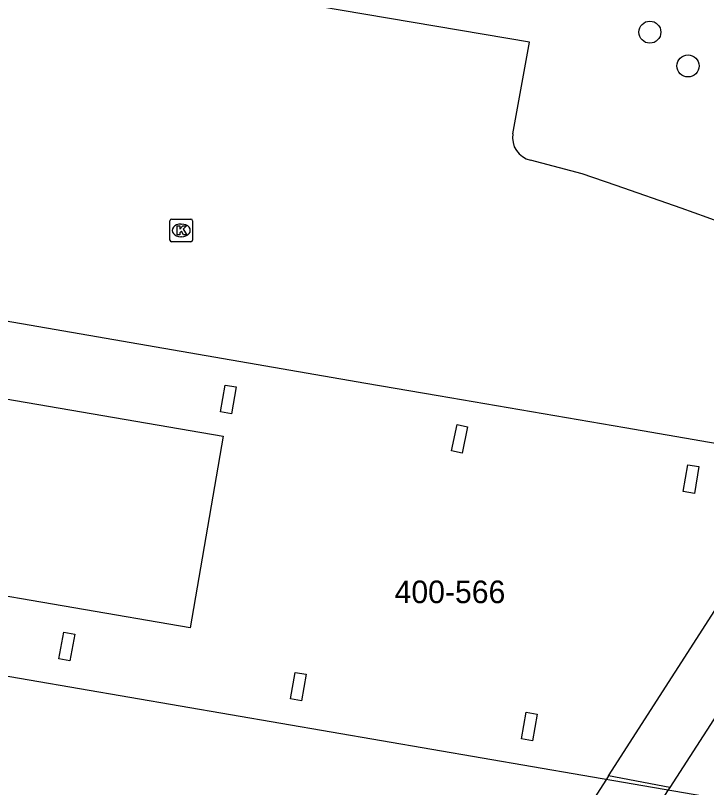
# Model space of a CAD drawing. Extents: x 161258 to 161838, y 380836 to 381727.
# Drawn here: x 161552.64 to 161583.27, y 381006.83 to 381041.03 of the extents above; entities that cross this region are included whole.
import ezdxf

# ---------------------------------------------------------------- set-up
doc = ezdxf.new("R2010")
doc.units = 0
for name, color, linetype in [('IMGEO_Boom', 7, 'Continuous'), ('IMGEO_Fietspad_gesloten', 7, 'Continuous'), ('IMGEO_Groenvoorziening', 7, 'Continuous'), ('IMGEO_Kolk', 7, 'Continuous'), ('IMGEO_Pand', 7, 'Continuous'), ('IMGEO_Pand_nummerreeks', 7, 'Continuous'), ('IMGEO_Pand_overbouw', 7, 'Continuous'), ('IMGEO_Voetpad_open', 7, 'Continuous')]:
    doc.layers.add(name, color=color, linetype=linetype)

msp = doc.modelspace()

# ---------------------------------------------------------------- linework, layer by layer
at = {"layer": 'IMGEO_Boom'}
for centre in [(161580.754, 381040.286), (161582.445, 381038.792)]:
    msp.add_circle(centre, 0.489, dxfattribs=at)
at = {"layer": 'IMGEO_Fietspad_gesloten'}
for points in [[(161590.696, 381020.856), (161581.633, 381006.84)], [(161581.633, 381006.84), (161581.562, 381006.731), (161578.938, 381002.688), (161504.207, 380887.394), (161498.991, 380879.345)]]:
    msp.add_lwpolyline(points, dxfattribs=at)
at = {"layer": 'IMGEO_Groenvoorziening'}
for points in [[(161574.684, 381035.789), (161575.416, 381039.839), (161557.769, 381042.844), (161555.301, 381043.416)], [(161592.569, 381028.461), (161585.018, 381031.447), (161583.298, 381032.072), (161582.135, 381032.494), (161579.268, 381033.49), (161577.753, 381034.017), (161575.464, 381034.622)]]:
    msp.add_lwpolyline(points, dxfattribs=at)
msp.add_arc((161575.684, 381035.613), 1.016, 170.0459, 257.4701, dxfattribs=at)
at = {"layer": 'IMGEO_Kolk'}
for p, q in [((161559.49, 381031.08), (161559.49, 381031.932)), ((161559.565, 381032.006), (161560.417, 381032.006)), ((161559.978, 381031.786), (161560.003, 381031.786)), ((161560.491, 381031.932), (161560.491, 381031.08)), ((161560.001, 381031.226), (161559.976, 381031.226)), ((161560.417, 381031.006), (161559.565, 381031.006))]:
    msp.add_line(p, q, dxfattribs=at)
for points in [[(161559.49, 381031.08), (161559.49, 381031.932)], [(161559.565, 381032.006), (161560.417, 381032.006)], [(161560.491, 381031.932), (161560.491, 381031.08)], [(161559.811, 381031.706), (161559.934, 381031.706), (161559.934, 381031.555), (161560.064, 381031.706), (161560.228, 381031.706), (161560.082, 381031.555), (161560.235, 381031.306), (161560.083, 381031.306), (161559.998, 381031.47), (161559.934, 381031.403), (161559.934, 381031.306), (161559.811, 381031.306), (161559.811, 381031.706)], [(161560.417, 381031.006), (161559.565, 381031.006)]]:
    msp.add_lwpolyline(points, dxfattribs=at)
for centre, start, end in [((161559.567, 381031.93), 91.552, 178.448), ((161559.567, 381031.93), 91.552, 178.448), ((161560.415, 381031.93), 1.552, 88.448), ((161560.415, 381031.93), 1.552, 88.448), ((161559.567, 381031.082), 181.552, 268.448), ((161559.567, 381031.082), 181.552, 268.448), ((161560.415, 381031.082), 271.552, 358.448), ((161560.415, 381031.082), 271.552, 358.448)]:
    msp.add_arc(centre, 0.0765, start, end, dxfattribs=at)
for centre, major_axis, ratio, start_param, end_param in [((161559.977, 381031.506), (-0.387, 0.002), 0.722429, 4.712389, 7.853982), ((161560.002, 381031.506), (-0.39, 0.002), 0.717154, 1.570796, 4.712389)]:
    msp.add_ellipse(centre, major_axis=major_axis, ratio=ratio, start_param=start_param, end_param=end_param, dxfattribs=at)
at = {"layer": 'IMGEO_Pand'}
for points in [[(161546.356, 381025.056), (161561.845, 381022.394), (161560.388, 381013.905), (161544.9, 381016.563), (161546.356, 381025.056)], [(161561.943, 381024.66), (161562.426, 381024.575), (161562.218, 381023.39), (161561.735, 381023.474), (161561.943, 381024.66)], [(161572.219, 381022.911), (161572.681, 381022.813), (161572.431, 381021.639), (161571.969, 381021.738), (161572.219, 381022.911)], [(161582.436, 381021.128), (161582.931, 381021.045), (161582.732, 381019.861), (161582.237, 381019.944), (161582.436, 381021.128)], [(161554.792, 381013.718), (161555.282, 381013.626), (161555.06, 381012.441), (161554.57, 381012.532), (161554.792, 381013.718)], [(161565.035, 381011.934), (161565.523, 381011.847), (161565.313, 381010.671), (161564.826, 381010.758), (161565.035, 381011.934)], [(161575.272, 381010.173), (161575.762, 381010.088), (161575.557, 381008.906), (161575.068, 381008.991), (161575.272, 381010.173)]]:
    msp.add_lwpolyline(points, dxfattribs=at)
at = {"layer": 'IMGEO_Pand_overbouw'}
for points in [[(161630.974, 380969.465), (161632.262, 380976.901), (161632.345, 380977.38), (161632.828, 380980.176), (161632.862, 380980.375), (161636.289, 381000.232), (161629.086, 381001.476), (161629.73, 381005.204), (161630.098, 381007.334), (161631.061, 381012.91), (161638.251, 381011.67), (161638.42, 381012.654), (161599.744, 381019.301), (161595.349, 381020.056), (161587.915, 381021.334), (161579.647, 381022.757), (161571.38, 381024.181), (161568.164, 381024.732), (161546.929, 381028.397), (161543.554, 381028.979), (161529.957, 381031.314), (161529.713, 381031.356), (161529.469, 381031.398), (161494.957, 381037.336)], [(161492.214, 381022.109), (161536.152, 381014.547), (161539.612, 381013.952), (161544.314, 381013.143), (161580.012, 381006.998), (161621.54, 380999.849), (161617.447, 380975.661), (161615.362, 380963.591)]]:
    msp.add_lwpolyline(points, dxfattribs=at)
at = {"layer": 'IMGEO_Voetpad_open'}
for points in [[(161578.923, 381007.348), (161587.915, 381021.334)], [(161578.923, 381007.348), (161578.828, 381007.201), (161576.218, 381003.146), (161558.236, 380975.49), (161556.737, 380973.185), (161556.123, 380972.241), (161554.834, 380970.332), (161546.174, 380956.722), (161540.302, 380947.69), (161515.878, 380910.106)], [(161581.633, 381006.84), (161578.923, 381007.348)]]:
    msp.add_lwpolyline(points, dxfattribs=at)

# ---------------------------------------------------------------- texts
at = {"layer": 'IMGEO_Pand_nummerreeks'}
msp.add_text('400-566', height=1, dxfattribs=at).set_placement((161569.443, 381015))

doc.saveas('drawing.dxf')
